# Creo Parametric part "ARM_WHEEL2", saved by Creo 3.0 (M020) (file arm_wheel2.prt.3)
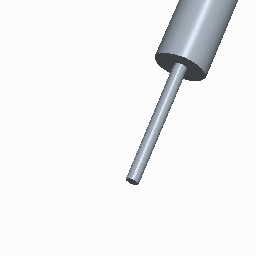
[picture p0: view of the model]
Units: millimeter Newton Second (mmNs); MM, TONNE, SECS

Created from: MMNS_PART_SOLID.PRT

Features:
  1. datum plane "RIGHT"
  2. datum plane "TOP"
  3. datum plane "FRONT"
  4. coordinate system
  5. sketch "Sketch 1"
  6. extrusion "Extrude 1"
  7. sketch "Sketch 2"
  8. extrusion "Extrude 2"
  9. sketch "Sketch 3"
  10. extrusion "Extrude 3"

Surfaces: 7 plane, 6 cylinder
